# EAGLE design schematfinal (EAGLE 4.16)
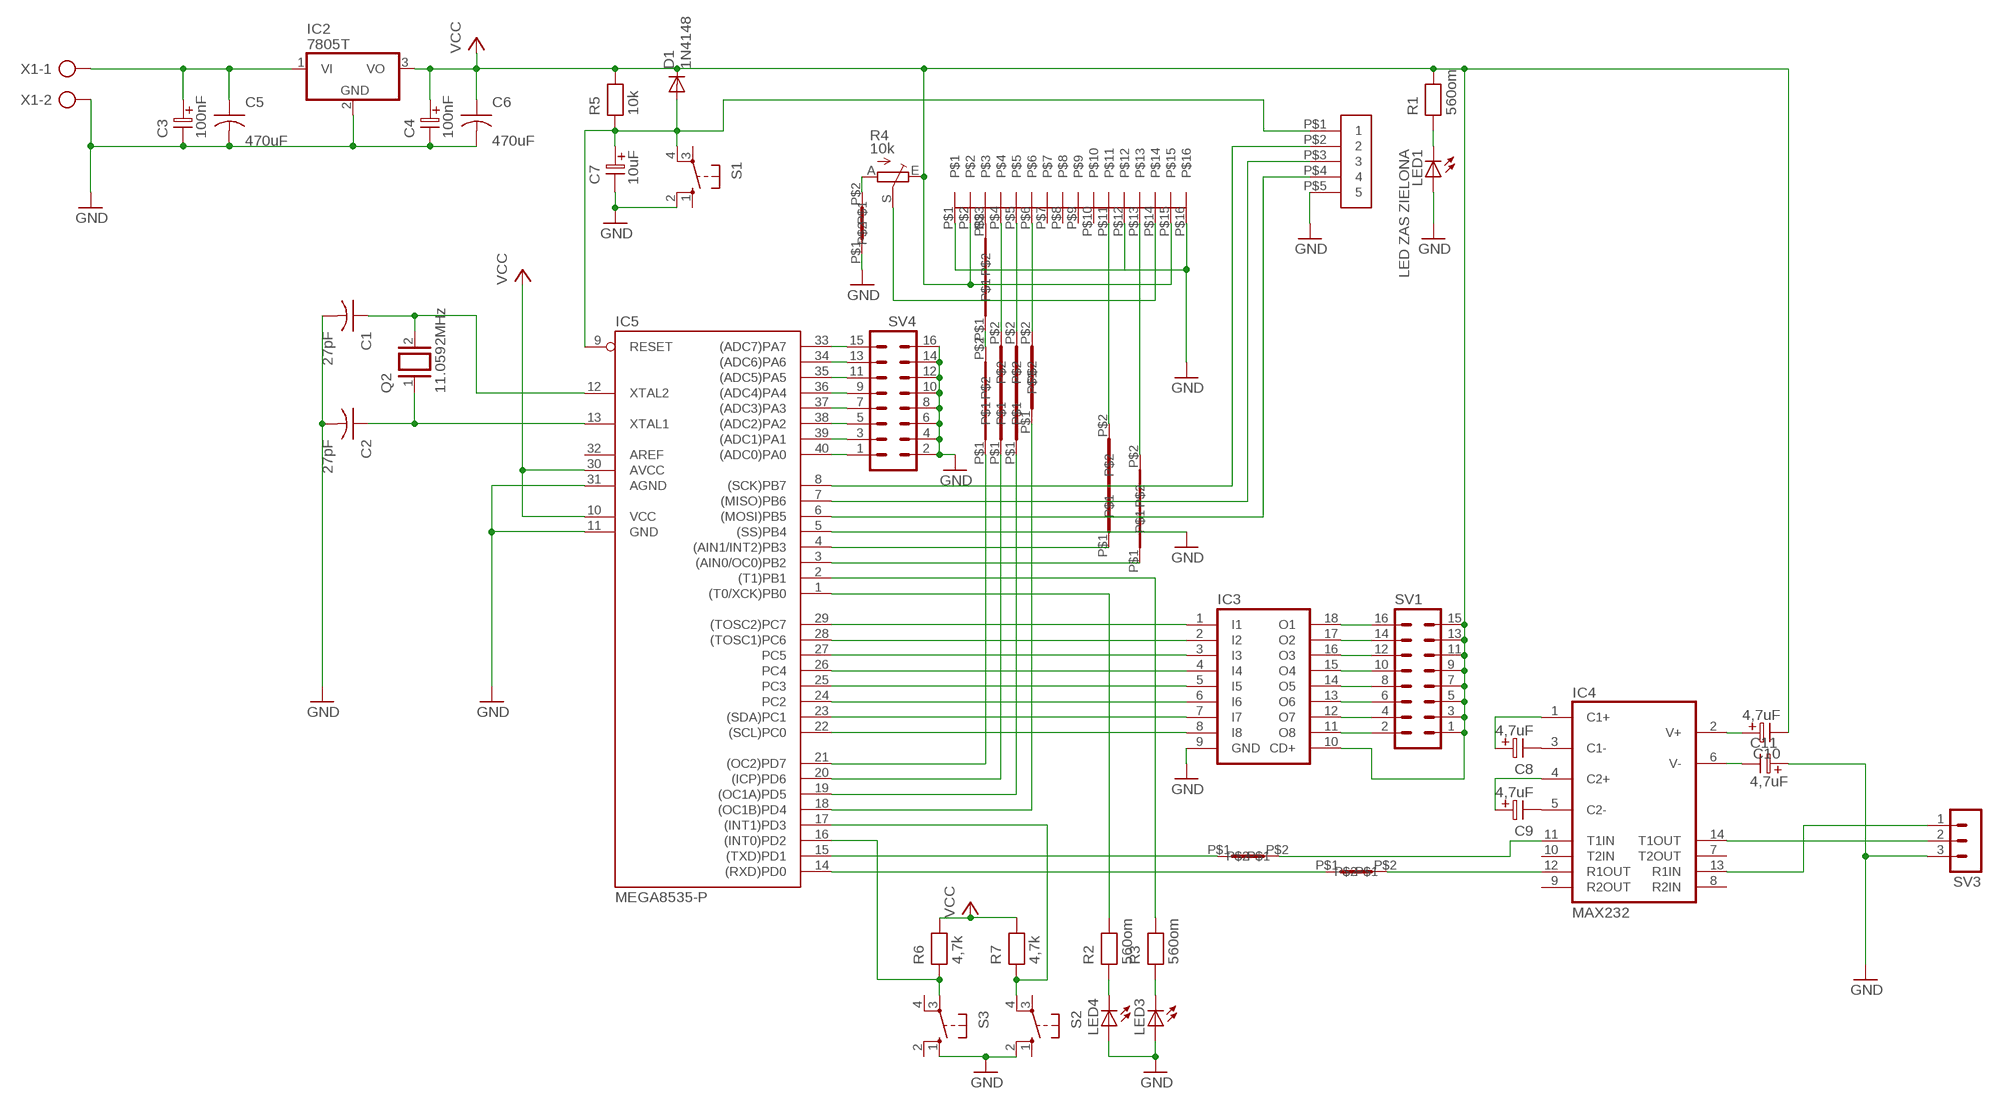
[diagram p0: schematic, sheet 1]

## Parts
C1  27pF  CAP-2,5  [C-2,5]
C2  27pF  CAP-2,5  [C-2,5]
C3  100nF  ELC-7,5  [ES-7,5]
C4  100nF  ELC-7,5  [ES-7,5]
C5  470uF  CAP-5  [C-5]
C6  470uF  CAP-5  [C-5]
C7  10uF  ELC-2,5  [ES-2,5]
C8  4,7uF  ELC-2,5  [ES-2,5]
C9  4,7uF  ELC-2,5  [ES-2,5]
C10  4,7uF  ELC-2,5  [ES-2,5]
C11  4,7uF  ELC-2,5  [ES-2,5]
D1  1N4148  [DO35-10]
IC2  7805T  [TO220H]
IC3  ULN2803A  [DIL18]
IC4  MAX232  [DIL16]
IC5  MEGA8535-P  [DIL40]
LED1  LED ZAS ZIELONA  LED5MM  [LED5MM]
LED3  LEDSQR2X5  [LED2X5]
LED4  LEDSQR2X5  [LED2X5]
Q2  11.0592MHz  XTAL/S  [QS]
R1  560om  RESEU-12,5  [R-12,5]
R2  560om  RESEU-12,5  [R-12,5]
R3  560om  RESEU-12,5  [R-12,5]
R4  10k  TRIM_EU-CA6V  [CA6V]
R5  10k  RESEU-12,5  [R-12,5]
R6  4,7k  RESEU-12,5  [R-12,5]
R7  4,7k  RESEU-12,5  [R-12,5]
S1  10-XX  [B3F-10XX]
S2  10-XX  [B3F-10XX]
S3  10-XX  [B3F-10XX]
SV1  MA08-2  [MA08-2]
SV3  MA03-1  [MA03-1]
SV4  MA08-2  [MA08-2]
U$1  16PINJUMP  [16PINJUMP]
U$2  5PIN  [5PIN]
U$3  ZW25MM  [ZW25MM]
U$4  ZW30MM  [ZW30MM]
U$5  ZW25MM  [ZW25MM]
U$6  ZW10MM  [ZW10MM]
U$7  ZW10MM  [ZW10MM]
U$8  ZW20MM  [ZW20MM]
U$9  ZW15MM  [ZW15MM]
U$10  ZW10MM  [ZW10MM]
U$11  ZW30MM  [ZW30MM]
U$12  ZW30MM  [ZW30MM]
X1  AK300/2  [AK300/2]

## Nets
GND: C1.2 C2.2 C3.2 C4.2 C5.2 C6.2 C7.2 C11.1 IC2.2(GND) IC3.9(GND) IC5.5((SS)PB4) IC5.11(GND) IC5.31(AGND) LED1.A LED3.A LED4.A S1.2(S1) S2.2(S1) S3.1(S) SV3.3 SV4.2 SV4.4 SV4.6 SV4.8 SV4.10 SV4.12 SV4.14 SV4.16 U$1.P$1 U$1.P$12 U$1.P$16 U$2.P$5 U$10.P$1 X1.2
N$1: C1.1 IC5.12(XTAL2) Q2.2
N$2: C2.1 IC5.13(XTAL1) Q2.1
N$3: IC5.34((ADC6)PA6) SV4.13
N$4: IC5.35((ADC5)PA5) SV4.11
N$5: IC5.36((ADC4)PA4) SV4.9
N$6: IC5.37((ADC3)PA3) SV4.7
N$7: IC5.38((ADC2)PA2) SV4.5
N$8: IC5.33((ADC7)PA7) SV4.15
N$9: IC5.39((ADC1)PA1) SV4.3
N$10: IC5.40((ADC0)PA0) SV4.1
N$11: IC3.18(O1) SV1.16
N$12: IC3.17(O2) SV1.14
N$13: IC3.16(O3) SV1.12
N$14: IC3.15(O4) SV1.10
N$15: C3.1 C5.1 IC2.1(VI) X1.1
N$16: C7.1 D1.A IC5.9(RESET) R5.1 S1.4(P1) U$2.P$1
N$17: IC3.14(O5) SV1.8
N$18: IC3.13(O6) SV1.6
N$19: IC3.12(O7) SV1.4
N$20: IC3.11(O8) SV1.2
N$21: C8.1 IC4.1(C1+)
N$22: C8.2 IC4.3(C1-)
N$23: C9.1 IC4.4(C2+)
N$24: C9.2 IC4.5(C2-)
N$25: U$1.P$11 U$3.P$2
N$26: IC5.15((TXD)PD1) U$6.P$1
N$27: C11.2 IC4.6(V-)
N$28: C10.1 IC4.2(V+)
N$29: IC4.14(T1OUT) SV3.2
N$30: IC4.13(R1IN) SV3.1
N$31: LED1.K(C) R1.1
N$32: IC5.1((T0/XCK)PB0) R2.2
N$33: U$1.P$13 U$4.P$2
N$34: IC5.2((T1)PB1) R3.2
N$35: LED4.K(C) R2.1
N$36: LED3.K(C) R3.1
N$37: IC4.11(T1IN) U$6.P$2
N$38: IC5.14((RXD)PD0) U$7.P$1
N$39: IC5.16((INT0)PD2) R6.1 S3.3(P)
N$40: IC5.17((INT1)PD3) R7.1 S2.4(P1)
N$41: IC5.21((OC2)PD7) U$12.P$1
N$42: IC5.20((ICP)PD6) U$5.P$1
N$43: IC5.8((SCK)PB7) U$2.P$2
N$44: IC5.7((MISO)PB6) U$2.P$3
N$45: IC5.6((MOSI)PB5) U$2.P$4
N$46: IC4.12(R1OUT) U$7.P$2
N$47: IC3.1(I1) IC5.29((TOSC2)PC7)
N$48: IC3.2(I2) IC5.28((TOSC1)PC6)
N$49: IC3.3(I3) IC5.27(PC5)
N$50: IC3.4(I4) IC5.26(PC4)
N$51: IC3.5(I5) IC5.25(PC3)
N$52: IC3.6(I6) IC5.24(PC2)
N$53: IC3.7(I7) IC5.23((SDA)PC1)
N$54: IC3.8(I8) IC5.22((SCL)PC0)
N$55: IC5.19((OC1A)PD5) U$8.P$1
N$56: IC5.18((OC1B)PD4) U$9.P$1
N$57: R4.S U$1.P$14
N$58: IC5.4((AIN1/INT2)PB3) U$3.P$1
N$59: IC5.3((AIN0/OC0)PB2) U$4.P$1
N$60: U$1.P$4 U$5.P$2
N$61: U$1.P$5 U$8.P$2
N$62: U$1.P$6 U$9.P$2
N$63: R4.A U$10.P$2
N$64: U$1.P$3 U$11.P$2
N$65: U$11.P$1 U$12.P$2
VCC: C4.1 C6.1 C10.2 D1.C IC2.3(VO) IC3.10(CD+) IC5.10(VCC) IC5.30(AVCC) R1.2 R4.E R5.2 R6.2 R7.2 SV1.1 SV1.3 SV1.5 SV1.7 SV1.9 SV1.11 SV1.13 SV1.15 U$1.P$2 U$1.P$15
Unconnected: IC4.7(T2OUT) IC4.8(R2IN) IC4.9(R2OUT) IC4.10(T2IN) S1.1(S) S1.3(P) S2.1(S) S2.3(P) S3.2(S1) S3.4(P1) U$1.P$7 U$1.P$8 U$1.P$9 U$1.P$10

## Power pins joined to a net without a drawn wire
AREF: IC5.32(AREF)
GND: IC4.15(GND)
VCC: IC4.16(VCC)

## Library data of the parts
C1 C2 = 0WT:CAP-2,5
C3 C4 = 0WT:ELC-7,5
C5 C6 = 0WT:CAP-5
C7-C11 = 0WT:ELC-2,5
D1 = 0WT:1N4148: DIODE
IC2 = 0WT:78*: Positive VOLTAGE REGULATOR Source: http://cache.national.com/ds/LM/LM78L05.pdf http://www.fairchildsemi.com/ds/LM/LM7805.pdf
IC3 = uln-udn:ULN2803A: DRIVER ARRAY
IC4 = maxim:MAX232: RS232 TRANSEIVER
IC5 = 0WT:MEGA8535-P: MICROCONTROLLER 8 Kbytes FLASH 512 bytes SRAM 512 bytes EEPROM USART 8-channel 10 bit ADC Source: avr.lbr
LED1 LED3 LED4 = 0WT:LED: LED
Q2 = special:XTAL/S: CRYSTAL
R1-R3 R5-R7 = 0WT:RESEU-12,5
R4 = pot:TRIM_EU-: POTENTIOMETER
S1-S3 = switch-omron:10-XX: OMRON SWITCH
SV1 SV4 = con-lstb:MA08-2: PIN HEADER
SV3 = con-lstb:MA03-1: PIN HEADER
U$1 = 0WT:16PINJUMP
U$2 = 0WT:5PIN
U$3 U$5 = 0WT:ZW25MM
U$4 U$11 U$12 = 0WT:ZW30MM
U$6 U$7 U$10 = 0WT:ZW10MM
U$8 = 0WT:ZW20MM
U$9 = 0WT:ZW15MM
X1 = con-ptr500:AK300/2: CONNECTOR

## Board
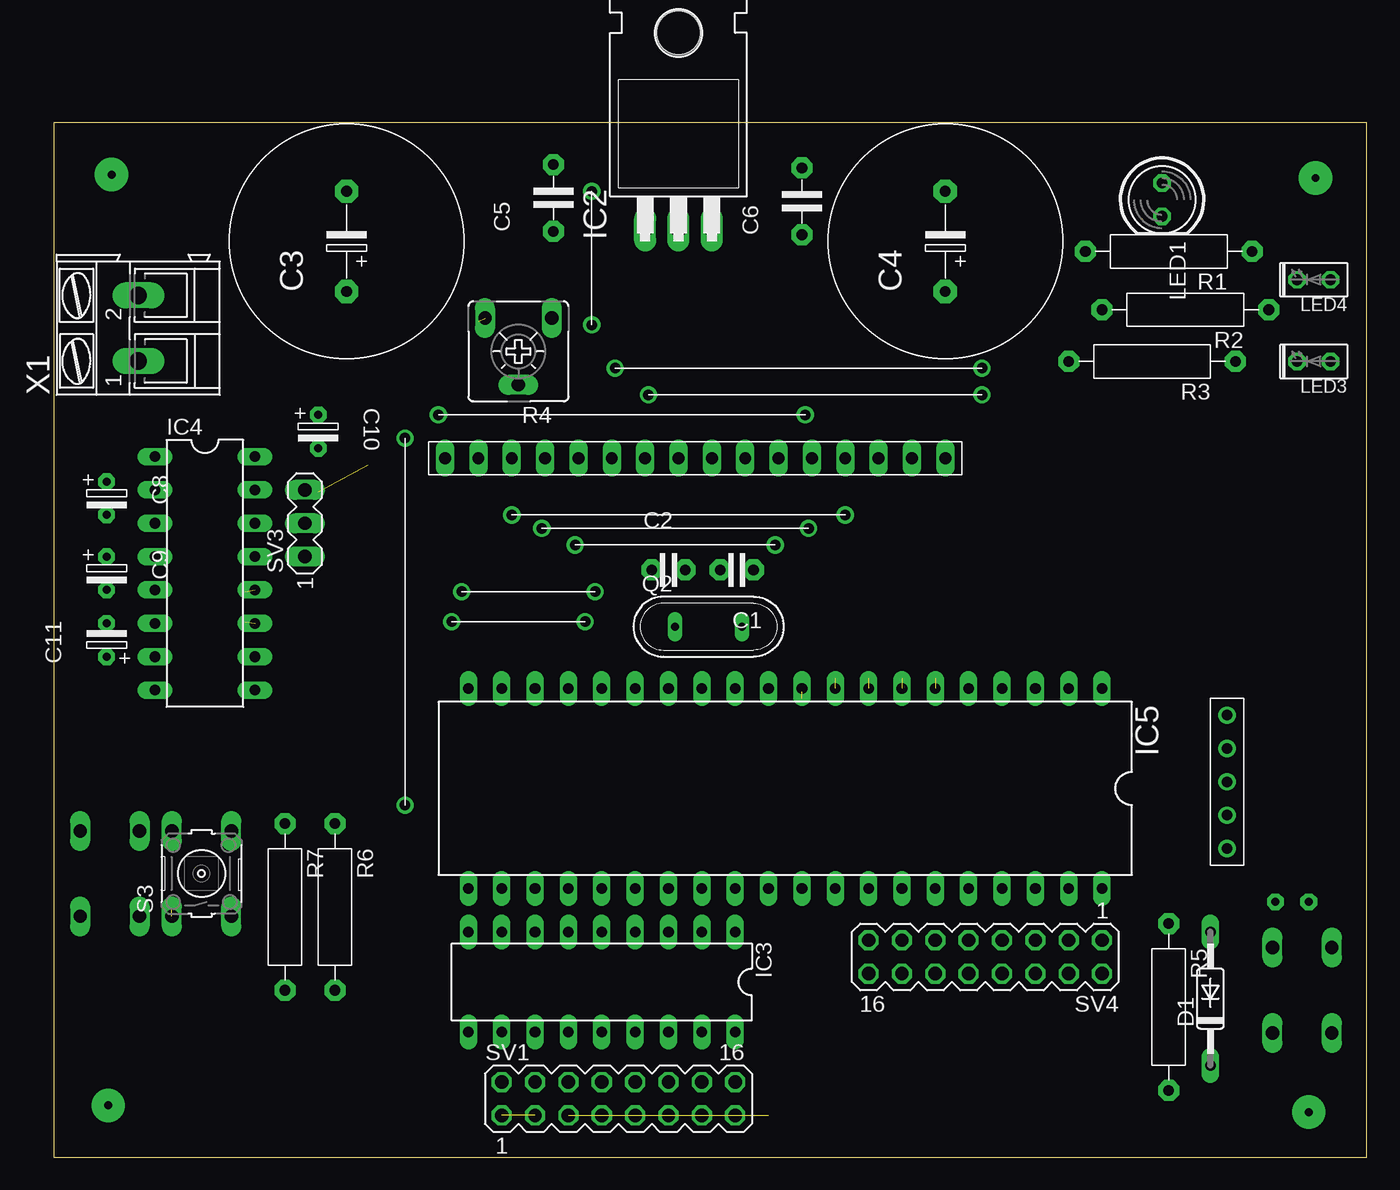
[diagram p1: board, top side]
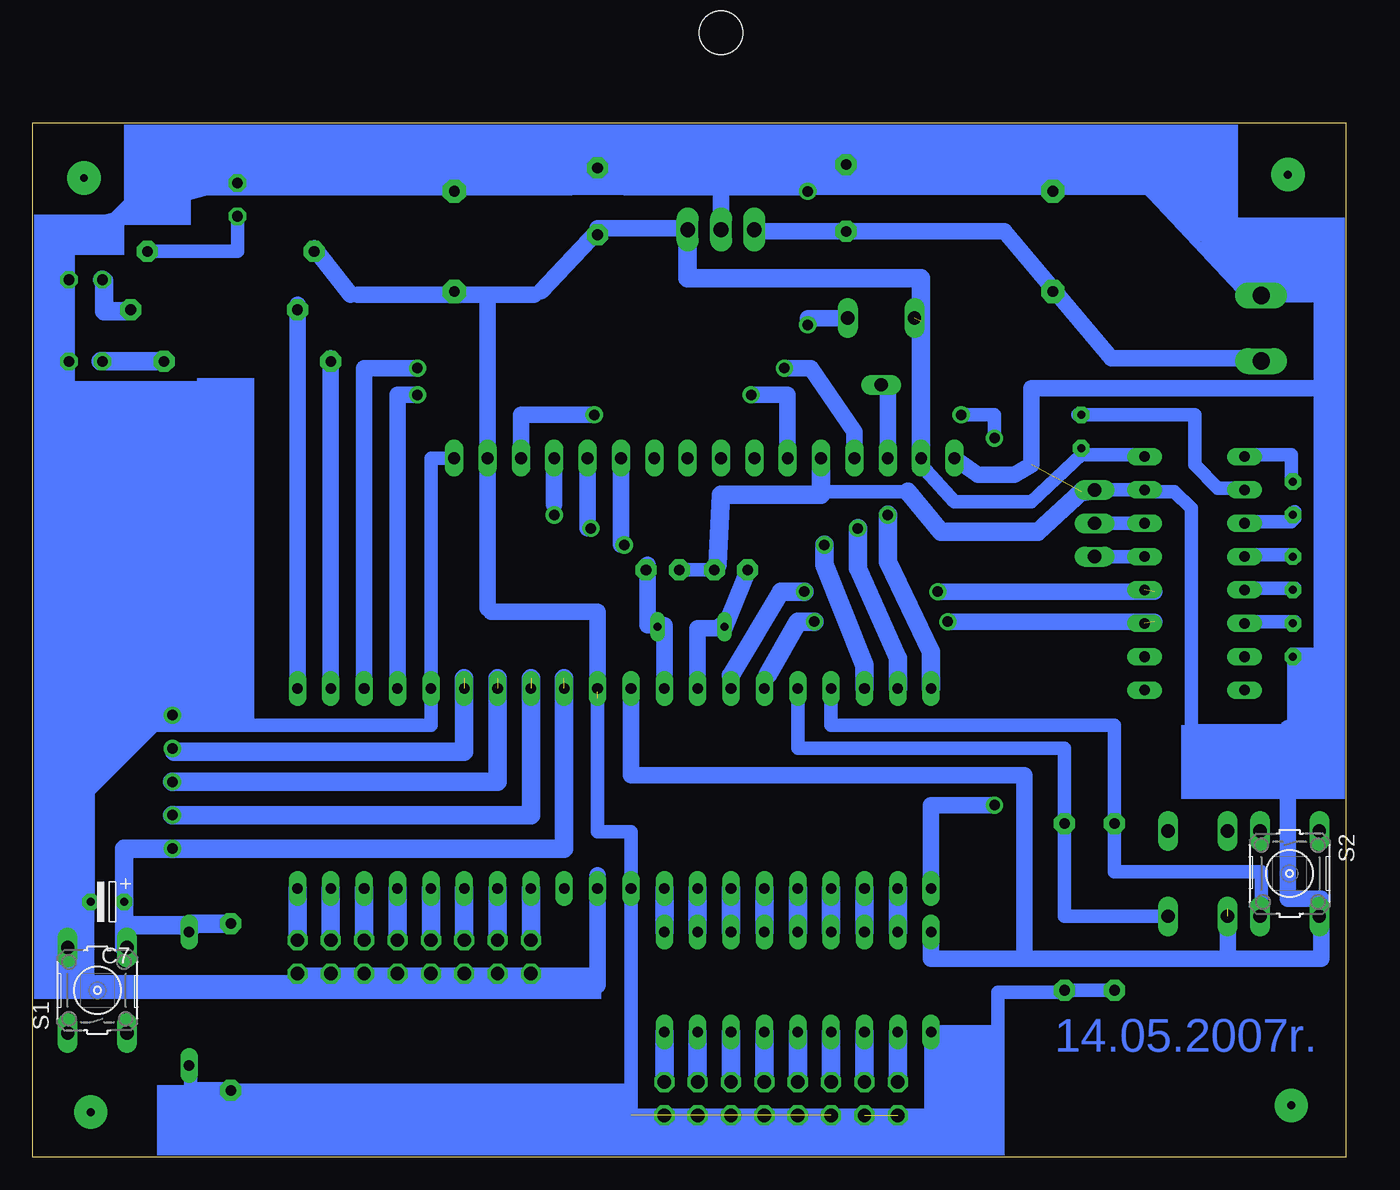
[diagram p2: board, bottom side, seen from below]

Size 100 x 78.73 mm. Coordinates in mm from the lower left corner, seen from the top.
Outline: 0,0 100,0 100,78.73 0,78.73 0,0
Copper layers (1*16): Top 0.035mm / dielectric 1.5mm / Bottom 0.035mm
Design rules "default": minimum track width 25mil, minimum drill 24mil, track to track 15mil, track to pad 15mil, pad to pad 8mil, via to via 8mil, smd to smd 8mil, copper to edge 25mil, drill to drill 8mil, minimum pad ring 10mil, minimum via ring 8mil, stop-mask expansion 4mil, vias tented up to drill 0mil, thermal gap 10mil

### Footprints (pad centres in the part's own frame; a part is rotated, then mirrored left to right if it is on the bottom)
C-2,5 = drill 0.813 pad 1.6 octagon: 1 -1.27,0; 2 1.27,0
ES-7,5 = drill 0.813 pad 1.778 octagon: 1 -3.81,0; 2 3.81,0
C-5 = drill 0.813 pad 1.6 octagon: 1 -2.54,0; 2 2.54,0
ES-2,5 = drill 0.61 pad 1.27 octagon: 1 -1.27,0; 2 1.27,0
DO35-10 = drill 0.813 long: A 5.08,0; C -5.08,0
TO220H = drill 1.118 long: 1 -2.54,-10.16; 2 0,-10.16; 3 2.54,-10.16 | hole 3.302: 0,4.826
DIL18 = drill 0.813 long: 1 -10.16,-3.81; 2 -7.62,-3.81; 3 -5.08,-3.81; 4 -2.54,-3.81; 5 0,-3.81; 6 2.54,-3.81; 7 5.08,-3.81; 8 7.62,-3.81; 9 10.16,-3.81; 10 10.16,3.81; 11 7.62,3.81; 12 5.08,3.81; 13 2.54,3.81; 14 0,3.81; 15 -2.54,3.81; 16 -5.08,3.81; 17 -7.62,3.81; 18 -10.16,3.81
DIL16 = drill 0.813 long: 1 -8.89,-3.81; 2 -6.35,-3.81; 3 -3.81,-3.81; 4 -1.27,-3.81; 5 1.27,-3.81; 6 3.81,-3.81; 7 6.35,-3.81; 8 8.89,-3.81; 9 8.89,3.81; 10 6.35,3.81; 11 3.81,3.81; 12 1.27,3.81; 13 -1.27,3.81; 14 -3.81,3.81; 15 -6.35,3.81; 16 -8.89,3.81
DIL40 = drill 0.813 long: 1 -24.13,-7.62; 2 -21.59,-7.62; 3 -19.05,-7.62; 4 -16.51,-7.62; 5 -13.97,-7.62; 6 -11.43,-7.62; 7 -8.89,-7.62; 8 -6.35,-7.62; 9 -3.81,-7.62; 10 -1.27,-7.62; 11 1.27,-7.62; 12 3.81,-7.62; 13 6.35,-7.62; 14 8.89,-7.62; 15 11.43,-7.62; 16 13.97,-7.62; 17 16.51,-7.62; 18 19.05,-7.62; 19 21.59,-7.62; 20 24.13,-7.62; 21 24.13,7.62; 22 21.59,7.62; 23 19.05,7.62; 24 16.51,7.62; 25 13.97,7.62; 26 11.43,7.62; 27 8.89,7.62; 28 6.35,7.62; 29 3.81,7.62; 30 1.27,7.62; 31 -1.27,7.62; 32 -3.81,7.62; 33 -6.35,7.62; 34 -8.89,7.62; 35 -11.43,7.62; 36 -13.97,7.62; 37 -16.51,7.62; 38 -19.05,7.62; 39 -21.59,7.62; 40 -24.13,7.62
LED5MM = drill 0.813 octagon: A -1.27,0; K 1.27,0
LED2X5 = drill 0.813 octagon: A -1.27,0; K 1.27,0
QS = drill 0.61 long: 1 -2.54,0; 2 2.54,0
R-12,5 = drill 0.813 pad 1.6 octagon: 1 -6.35,0; 2 6.35,0
CA6V = drill 1.016 long: A -2.54,-2.54; E 2.54,-2.54; S 0,2.54
B3F-10XX = drill 1.016 long: 1 -3.251,2.261; 2 3.251,2.261; 3 -3.251,-2.261; 4 3.251,-2.261
MA08-2 = drill 1.016 octagon: 1 -8.89,-1.27; 2 -8.89,1.27; 3 -6.35,-1.27; 4 -6.35,1.27; 5 -3.81,-1.27; 6 -3.81,1.27; 7 -1.27,-1.27; 8 -1.27,1.27; 9 1.27,-1.27; 10 1.27,1.27; 11 3.81,-1.27; 12 3.81,1.27; 13 6.35,-1.27; 14 6.35,1.27; 15 8.89,-1.27; 16 8.89,1.27
MA03-1 = drill 1.016 long: 1 -2.54,0; 2 0,0; 3 2.54,0
16PINJUMP = drill 0.9 pad 1.016 long: P$1 -19.05,0; P$2 -16.51,0; P$3 -13.97,0; P$4 -11.43,0; P$5 -8.89,0; P$6 -6.35,0; P$7 -3.81,0; P$8 -1.27,0; P$9 1.27,0; P$10 3.81,0; P$11 6.35,0; P$12 8.89,0; P$13 11.43,0; P$14 13.97,0; P$15 16.51,0; P$16 19.05,0
5PIN = drill 0.8 round: P$1 -5.08,0; P$2 -2.54,0; P$3 0,0; P$4 2.54,0; P$5 5.08,0
ZW25MM = drill 0.8 round: P$1 -12.7,0; P$2 12.7,0
ZW30MM = drill 0.8 round: P$1 -15.24,0; P$2 12.7,0
ZW10MM = drill 0.8 round: P$1 -5.08,0; P$2 5.08,0
ZW20MM = drill 0.8 round: P$1 -10.16,0; P$2 10.16,0
ZW15MM = drill 0.8 round: P$1 -7.62,0; P$2 7.62,0
AK300/2 = drill 1.321 long: 1 -2.515,0; 2 2.489,0

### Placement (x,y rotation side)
C1  52.03,44.7 180 top
C2  46.82,44.7 0 top
C3  22.31,69.72 90 top
C4  67.91,69.72 90 top
C5  38.06,73.02 90 top
C6  56.98,72.77 90 top
C7  94.32,19.43 180 bottom
C8  4.03,50.16 270 top
C9  4.03,44.45 270 top
C10  20.16,55.24 270.1 top
C11  4.03,39.37 90 top
D1  88.1,12.06 90 top
IC2  47.59,80.77 0 top
IC3  41.74,13.33 180 top
IC4  11.52,44.45 270 top
IC5  55.71,28.06 180 top
LED1  84.42,72.89 270 top
LED3  95.97,60.57 180 top
LED4  95.97,66.8 180 top
Q2  49.87,40.38 0 top
R1  84.92,68.96 180 top
R2  86.2,64.51 180 top
R3  83.66,60.57 180 top
R4  35.39,61.34 180 top
R5  84.92,11.42 270 top
R6  21.43,19.04 270 top
R7  17.62,19.04 270 top
S1  95.09,12.7 90 bottom
S2  4.28,21.59 270 bottom
S3  11.27,21.59 90 top
SV1  43.01,4.44 0 top
SV3  19.14,48.26 90 top
SV4  70.95,15.23 180 top
U$1  48.86,53.21 180 top
U$2  89.37,28.57 90 top
U$3  58,58.03 180 top
U$4  55.46,60.07 180 top
U$5  47.59,48.89 0 top
U$6  35.39,40.76 180 top
U$7  36.16,43.05 180 top
U$8  47.33,47.87 0 top
U$9  47.33,46.6 0 top
U$10  40.98,68.45 270 top
U$11  44.54,56.51 0 top
U$12  26.76,42.03 90 top
X1  6.44,63.11 90 top

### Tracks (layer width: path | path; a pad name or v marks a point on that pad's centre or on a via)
GND  (2 unrouted)
  Bottom 0.406: 23.96,52.7 23.96,58.8 1.61,58.8 1.61,33.65 2.38,33.65 2.38,29.59 11.52,29.59 11.52,49.4 13.3,50.92 19.9,50.67 | 20.16,50.67 20.41,50.67 20.41,50.16 20.16,50.67
  Bottom 0.635: IC5.31 56.98,14.09 62.06,14.09 SV4.16 62.57,14.09 64.1,14.09 SV4.14 65.11,14.09 66.64,14.09 SV4.12 67.65,14.09 69.18,14.09 SV4.10 70.19,14.09 71.72,14.09 SV4.8 72.73,14.09 74.26,14.09 SV4.6 75.27,14.09 76.8,14.09 SV4.4 77.81,14.09 79.34,14.09 SV4.2 80.35,13.08 97.12,13.08 97.12,15.11 S1.2 97.37,17.14 97.37,20.95 C7.2 95.59,27.81 90.01,33.4 U$2.P$5 90.01,33.9 97.12,33.9 97.12,54.73 LED3.A 97.12,55.75 97.12,60.32 LED4.A 97.12,61.34 97.12,70.73 LED1.A 84.92,77.08 94.83,70.23 | 47.59,70.73 IC2.2 | 47.84,45.08 C2.2 | 2.12,19.68 S2.2 | 15.33,50.67 15.08,50.67 | 11.77,32.63 4.41,32.63 4.15,32.63 4.15,37.97 C11.1 4.15,38.48 2.12,38.48 2.12,65.4 4.66,65.4 X1.2 7.46,65.4 15.33,73.78 21.93,73.78 C3.2 22.95,74.04 23.96,75.05 37.68,75.05 C5.2 39.2,75.56 40.73,74.04 U$10.P$1 47.59,73.53 54.95,73.53 56.48,75.05 C6.2 57.49,75.05 59.02,73.53 C4.2 91.53,73.53
  Bottom 1.016: IC4.15 15.08,50.8 15.08,50.67 | IC4.15 SV3.3 | U$2.P$5 86.96,33.65 86.96,32.89 69.69,32.89 IC5.5 69.69,53.21 U$1.P$1 | 11.77,32.63 11.77,49.4 13.04,50.67 15.33,50.67 IC4.15 | C2.2 48.09,44.83 48.22,44.7 C1.2 | 40.22,50.67 39.97,50.67 33.36,50.67
  Bottom 1.27: 91.53,73.53 94.83,70.23 | 47.59,73.53 47.59,70.73 | 4.41,19.68 2.12,19.68 | 4.41,19.68 4.41,32.63 | 4.41,19.68 1.87,19.68 1.87,15.11 8.98,15.11 | 8.98,15.11 8.98,18.92 | 8.98,15.11 24.47,15.11 | 24.47,15.11 31.59,15.11 IC3.9 | U$1.P$16 28.03,51.94 25.23,51.94 23.96,52.7 23.96,58.54 1.36,58.54 | IC5.11 54.45,29.08 24.47,29.08 24.47,15.11
  Bottom 1.422: 47.84,45.08 47.59,50.41 39.97,50.41 39.97,50.67 U$1.P$12 39.97,53.46 | SV3.3 19.9,50.67 20.16,50.67 23.46,47.62 30.82,47.62 33.36,50.67
N$1
  Bottom 0.635: Q2.2 51.9,40
  Bottom 1.27: IC5.12 51.9,40.51 52.41,40.51 | 52.41,40.51 Q2.2 | 53.17,45.08 53.17,44.7 | 53.17,44.7 C1.1 | 52.41,40.51 53.17,40.51 53.17,44.7
N$2
  Bottom 0.635: 47.33,40.25 Q2.1
  Bottom 1.27: IC5.13 49.36,40.25 47.33,40.25 | 47.59,40.38 47.59,40.51 | Q2.1 47.59,40.38 | 47.33,40.25 47.59,40.38 | C2.1 45.55,44.57 47.33,40.25
N$3
  Bottom 1.422: SV4.13 IC5.34
N$4
  Bottom 1.422: SV4.11 IC5.35
N$5
  Bottom 1.422: SV4.9 IC5.36
N$6
  Bottom 1.422: SV4.7 IC5.37
N$7
  Bottom 1.422: SV4.5 IC5.38
N$8
  Bottom 1.422: SV4.15 IC5.33
N$9
  Bottom 1.422: SV4.3 IC5.39
N$10
  Bottom 1.422: SV4.1 IC5.40
N$11
  Bottom 1.422: SV1.16 IC3.18
N$12
  Bottom 1.422: SV1.14 IC3.17
N$13
  Bottom 1.422: SV1.12 IC3.16
N$14
  Bottom 1.422: SV1.10 IC3.15
N$15
  Bottom 0.635: IC2.1 44.28,70.48 C5.1 26,70.48 21.68,65.4 | 21.68,65.4 17.87,60.83 8.22,60.83 X1.1 | C3.1 21.68,65.4
  Bottom 1.27: 45.05,70.48 26,70.48 17.87,60.83
N$16  (1 unrouted)
  Bottom 0.635: C7.1 93.05,20.7 | 93.05,17.14 S1.4 93.05,17.65
  Bottom 1.422: 59.52,36.44 59.52,23.49 U$2.P$1 93.05,23.49 C7.1 | C7.1 93.05,19.17 | S1.4 93.05,15.95 93.05,17.65 | C7.1 93.05,17.65 | R5.1 87.97,17.77 87.97,17.39 88.48,17.65 | 88.48,17.65 D1.A | 93.05,17.65 88.48,17.65
N$17
  Bottom 1.422: SV1.8 IC3.14
N$18
  Bottom 1.422: SV1.6 IC3.13
N$19
  Bottom 1.422: SV1.4 IC3.12
N$20
  Bottom 1.422: SV1.2 IC3.11
N$21
  Bottom 1.016: C8.1 4.15,51.56 4.15,53.46 7.58,53.46 IC4.1
N$22
  Bottom 1.016: IC4.3 7.58,48.38 4.15,48.38 3.9,48.64 3.9,49.02 | 3.9,49.14 3.9,49.02 | 3.9,49.02 C8.2
N$23
  Bottom 1.016: C9.1 4.15,45.84 7.58,45.84 IC4.4
N$24
  Bottom 1.016: C9.2 3.9,43.3 7.58,43.3 IC4.5
N$25
  Bottom 1.27: U$1.P$11 42.51,58.03 U$3.P$2
N$26
  Bottom 0.635: IC5.15 44.03,36.7
  Bottom 1.422: 44.03,36.7 41.74,40.76 U$6.P$1
N$27
  Bottom 1.016: C11.2 3.9,40.76 7.58,40.76 IC4.6
N$28
  Bottom 1.016: IC4.2 7.84,50.92 9.74,50.92 11.52,52.7 11.52,56.51 C10.1 | 20.41,56.51 C10.1 | C10.1
N$29
  Bottom 1.016: SV3.2 IC4.14 15.33,48.13
N$30
  Bottom 1.016: SV3.1 IC4.13 15.33,45.59
N$31
  Bottom 1.016: LED1.K 84.42,68.96 R1.1
N$32
  Bottom 1.27: 79.84,64.89 R2.2 IC5.1
N$33
  Bottom 1.27: U$1.P$13 37.43,55.24 40.73,60.07 U$4.P$2
N$34
  Bottom 1.27: 77.31,60.83 R3.2 IC5.2
N$35
  Bottom 0.813: 94.58,66.92 94.58,66.8 LED4.K
  Bottom 1.422: LED4.K 94.58,66.67 94.58,64.38 92.55,64.38 R2.1
N$36
  Bottom 1.422: 94.83,60.57 LED3.K R3.1
N$37  (1 unrouted)
  Bottom 1.27: U$6.P$2 14.57,40.76
N$38
  Bottom 0.635: U$7.P$1 41.74,43.05 | 46.82,36.7 IC5.14
  Bottom 1.422: 46.82,36.7 43.01,43.05 U$7.P$1
N$39
  Bottom 1.016: 21.43,25.52 21.43,31.11 41.74,31.11 IC5.16 | 21.43,25.52 R6.1 | S3.3 21.43,18.33 21.43,25.52
N$40
  Bottom 1.016: S2.4 6.44,18.33 6.44,21.71 17.62,21.71 R7.1 17.62,32.89 39.2,32.89 IC5.17
N$41
  Bottom 1.27: U$12.P$1 31.59,26.79 IC5.21 31.59,20.19
N$42
  Bottom 1.422: IC5.20 31.59,38.48 34.89,45.33 U$5.P$1
N$43  (1 unrouted)
  Bottom 1.422: U$2.P$2 62.06,26.03 62.06,36.44
N$44  (1 unrouted)
  Bottom 1.422: U$2.P$3 64.61,28.57 64.61,36.44
N$45  (1 unrouted)
  Bottom 0.635: U$2.P$4 89.24,30.86
  Bottom 1.422: 89.24,30.86 67.15,30.86 67.15,36.44
N$46  (1 unrouted)
  Bottom 1.27: U$7.P$2 14.57,43.05
N$47
  Bottom 1.422: IC3.1 IC5.29
N$48
  Bottom 1.422: IC3.2 IC5.28
N$49
  Bottom 1.422: IC3.3 IC5.27
N$50
  Bottom 1.422: IC3.4 IC5.26
N$51
  Bottom 1.422: IC3.5 IC5.25
N$52
  Bottom 1.422: IC3.6 IC5.24
N$53
  Bottom 1.422: IC3.7 IC5.23
N$54
  Bottom 1.422: IC3.8 IC5.22
N$55
  Bottom 1.422: IC5.19 34.12,37.97 37.17,44.83 U$8.P$1
N$56
  Bottom 1.422: IC5.18 36.66,37.46 39.71,45.08 U$9.P$1
N$57
  Bottom 1.27: R4.S 34.89,58.8 U$1.P$14
N$58
  Bottom 0.635: IC5.4 72.23,36.95
  Bottom 1.27: 72.23,35.43 IC5.4 72.23,58.03 U$3.P$1
N$59
  Bottom 1.27: IC5.3 74.77,60.07 U$4.P$1
N$60
  Bottom 0.635: U$5.P$2 60.29,49.65
  Bottom 1.27: 60.29,53.72 U$1.P$4 60.29,49.65
N$61
  Bottom 1.27: 57.75,53.46 U$1.P$5 57.75,47.87 U$8.P$2
N$62
  Bottom 1.27: 55.21,53.72 U$1.P$6 55.21,46.6 U$9.P$2
N$63
  Bottom 1.27: U$10.P$2 40.98,63.88 R4.A
N$64
  Bottom 1.27: U$1.P$3 62.83,56.51 U$11.P$2
N$65
  Bottom 1.016: U$12.P$2 26.76,56.51 U$11.P$1
N$66  (via drill 0.6 pad 2.54)
  other vias: 4.15,3.93
N$67  (via drill 0.6 pad 2.54)
  other vias: 4.41,74.8
N$68  (via drill 0.6 pad 2.54)
  other vias: 96.1,74.54
N$69  (via drill 0.6 pad 2.54)
  other vias: 95.59,3.42
N$70
  Bottom 1.27: 50.38,70.73 56.98,70.73
N$71
  Bottom 1.27: 17.62,60.83 5.93,60.83
N$72
  Bottom 1.27: 56.98,70.48 61.3,65.91
N$73
  Bottom 1.27: 61.81,65.65 75.27,65.65
N$74
  Bottom 1.27: 75.78,65.65 78.58,69.21
N$76
  Bottom 1.27: 56.98,13.08 56.98,21.46
VCC  (9 unrouted)
  Bottom 0.635: 65.62,65.91 65.62,54.22 U$1.P$2 65.11,52.19 65.11,41.52 | 65.62,65.91 C4.1 75.78,65.91 77.81,67.94 R1.2 | 65.62,65.91 61.56,65.91 57.49,69.97 C6.1 56.48,70.48 50.89,70.48 IC2.3 50.13,70.48 | 56.98,35.43 IC5.10 56.98,41.52
  Bottom 1.016: 56.98,34.92 56.98,24.76 54.45,24.76 IC5.30 54.45,5.2 | 54.45,5.2 54.45,3.17 SV1.1 31.59,3.17 IC3.10 26.5,9.52 26.5,12.57 21.43,12.57 R6.2 R7.2 17.62,12.57 | D1.C 87.97,6.98 87.97,5.2 84.92,5.2 R5.2 | R5.2 84.92,4.95 | R5.2 54.45,5.08 54.45,5.2 | 20.16,53.46 C10.2 | IC4.16 15.46,53.46 20.16,53.46 | 20.16,53.46 23.96,49.91 29.81,49.91 32.35,52.7 U$1.P$15
  Bottom 1.27: 65.37,54.22 65.37,53.97 | 65.37,54.22 65.37,65.4 | 65.37,54.22 65.37,41.78 65.11,41.52 56.98,41.52 56.98,35.43
  Bottom 1.422: 50.13,70.48 50.13,66.92 32.35,66.92 32.35,62.86 | U$1.P$15 32.35,62.86 | 32.35,62.86 32.35,63.62
(copper drawn outside any net)
  shapes: Bottom area x64

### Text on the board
Bottom: 14.05.2007r.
